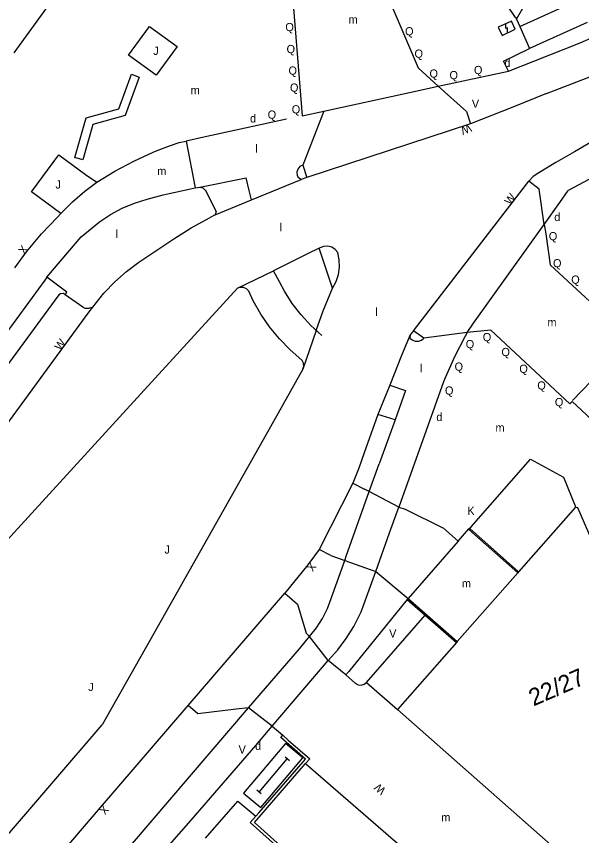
# Model space of a CAD drawing. Extents: x 134999 to 136502, y 457398 to 459002.
# Drawn here: x 135781.6 to 135816.2, y 457565.2 to 457615.2 of the extents above; entities that cross this region are included whole.
import ezdxf

# ---------------------------------------------------------------- set-up
doc = ezdxf.new("R2010")
doc.units = 0
for name, color, linetype in [('RI_DGTB_18', 7, 'Continuous'), ('RI_DGTB_2', 7, 'Continuous'), ('RI_DGTB_29', 7, 'Continuous'), ('RI_DGTB_30', 7, 'Continuous'), ('RI_DGTB_31', 7, 'Continuous'), ('RI_DGTB_32', 7, 'Continuous'), ('RI_DGTB_35', 7, 'Continuous'), ('RI_DGTB_43', 7, 'Continuous'), ('RI_DGTB_53', 7, 'Continuous')]:
    doc.layers.add(name, color=color, linetype=linetype)

msp = doc.modelspace()

# ---------------------------------------------------------------- linework, layer by layer
at = {"layer": 'RI_DGTB_18'}
msp.add_lwpolyline([(135812.201, 457615.04), (135812.669, 457615.857), (135810.956, 457618.449)], dxfattribs=at)
at = {"layer": 'RI_DGTB_2'}
for p, q in [((135812.279, 457581.22), (135808.583, 457577.024)), ((135812.332, 457581.281), (135812.279, 457581.22)), ((135808.53, 457576.964), (135804.925, 457572.871)), ((135808.583, 457577.024), (135808.53, 457576.964)), ((135818.002, 457561.354), (135804.925, 457572.871))]:
    msp.add_line(p, q, dxfattribs=at)
for points in [[(135784.404, 457617.014), (135781.488, 457612.993)], [(135815.841, 457585.222), (135815.811, 457585.23), (135812.332, 457581.281)], [(135815.945, 457585.195), (135815.841, 457585.222)], [(135824.803, 457564.892), (135820.25, 457575.305), (135819.517, 457574.985), (135818.517, 457577.282), (135819.251, 457577.601), (135815.945, 457585.195)]]:
    msp.add_lwpolyline(points, dxfattribs=at)
at = {"layer": 'RI_DGTB_29'}
for points in [[(135811.324, 457614.054), (135812.133, 457614.428), (135811.898, 457614.936), (135811.089, 457614.562), (135811.324, 457614.054)], [(135811.662, 457614.253), (135811.661, 457614.518), (135811.561, 457614.472), (135811.56, 457614.737)], [(135799.149, 457569.909), (135798.097, 457570.801), (135795.522, 457567.768), (135796.574, 457566.875), (135799.149, 457569.909)], [(135796.477, 457567.827), (135798.194, 457569.849)], [(135798.326, 457569.738), (135798.063, 457569.961)], [(135796.609, 457567.715), (135796.346, 457567.938)]]:
    msp.add_lwpolyline(points, dxfattribs=at)
at = {"layer": 'RI_DGTB_31'}
msp.add_line((135819.094, 457595.34), (135815.624, 457591.747), dxfattribs=at)
at = {"layer": 'RI_DGTB_32'}
for points in [[(135787.901, 457609.579), (135788.687, 457611.687), (135789.156, 457611.512)], [(135789.156, 457611.512), (135788.282, 457609.167)], [(135785.905, 457609.015), (135787.901, 457609.579)], [(135786.31, 457608.61), (135785.699, 457606.454), (135785.218, 457606.59), (135785.905, 457609.015)], [(135788.282, 457609.167), (135786.31, 457608.61)]]:
    msp.add_lwpolyline(points, dxfattribs=at)
at = {"layer": 'RI_DGTB_53'}
for p, q in [((135811.716, 457611.879), (135813.267, 457612.487)), ((135807.421, 457610.948), (135809.155, 457609.413)), ((135799.116, 457609.14), (135800.437, 457609.422)), ((135800.437, 457609.422), (135799.14, 457606.127)), ((135809.155, 457609.413), (135809.404, 457608.653)), ((135792.015, 457607.602), (135792.579, 457604.741)), ((135799.14, 457606.127), (135799.389, 457605.366)), ((135796.016, 457604.015), (135799.045, 457605.261)), ((135813.595, 457604.663), (135812.962, 457605.152)), ((135813.904, 457602.509), (135813.595, 457604.663)), ((135793.795, 457603.102), (135796.016, 457604.015)), ((135792.328, 457602.292), (135793.479, 457602.932)), ((135793.795, 457603.102), (135793.479, 457602.932)), ((135809.581, 457596.472), (135813.904, 457602.509)), ((135783.512, 457599.293), (135785.603, 457601.743)), ((135781.546, 457599.848), (135782.266, 457600.825)), ((135800.257, 457601.105), (135800.137, 457601.056)), ((135795.155, 457598.605), (135797.356, 457599.68)), ((135797.728, 457598.991), (135797.356, 457599.68)), ((135809.202, 457595.905), (135809.581, 457596.472)), ((135799.963, 457596.022), (135799.153, 457593.659)), ((135809.202, 457595.905), (135806.538, 457595.555)), ((135809.202, 457595.905), (135809.045, 457595.643)), ((135804.789, 457590.559), (135803.732, 457590.898)), ((135802.211, 457586.696), (135802.924, 457586.332)), ((135804.44, 457583.663), (135805.01, 457585.243)), ((135809.35, 457583.936), (135809.297, 457583.876)), ((135809.297, 457583.876), (135812.279, 457581.22)), ((135809.35, 457583.936), (135812.332, 457581.281)), ((135808.64, 457583.147), (135805.577, 457579.653)), ((135800.859, 457582.286), (135800.147, 457582.649)), ((135803.612, 457581.306), (135805.577, 457579.653)), ((135805.526, 457579.591), (135801.952, 457575.2)), ((135805.577, 457579.653), (135805.526, 457579.591)), ((135805.526, 457579.591), (135806.623, 457578.631)), ((135805.577, 457579.653), (135808.583, 457577.024)), ((135803.031, 457574.528), (135806.623, 457578.631)), ((135806.623, 457578.631), (135808.53, 457576.964)), ((135798.94, 457576.582), (135799.561, 457577.33)), ((135800.694, 457575.868), (135799.561, 457577.33)), ((135803.031, 457574.528), (135804.925, 457572.871)), ((135797.277, 457571.851), (135795.829, 457572.971)), ((135780.361, 457564.339), (135786.894, 457571.924)), ((135796.598, 457566.445), (135799.321, 457569.571)), ((135799.321, 457569.571), (135811.178, 457559.3))]:
    msp.add_line(p, q, dxfattribs=at)
for points in [[(135799.982, 457626.659), (135806.199, 457612.074), (135807.421, 457610.948)], [(135795.358, 457624.682), (135796.194, 457622.7), (135798.426, 457617.505), (135799.116, 457609.14)], [(135812.15, 457615.149), (135810.236, 457618.01)], [(135812.411, 457614.592), (135816.096, 457616.29)], [(135812.15, 457615.149), (135812.201, 457615.04)], [(135812.201, 457615.04), (135812.411, 457614.592)], [(135816.535, 457614.839), (135813.011, 457613.25)], [(135789.779, 457614.606), (135791.46, 457613.376), (135790.18, 457611.627), (135788.499, 457612.858), (135789.779, 457614.606)], [(135812.411, 457614.592), (135813.011, 457613.25)], [(135813.267, 457612.487), (135816.089, 457613.611), (135816.938, 457613.966)], [(135811.716, 457611.879), (135811.413, 457612.485), (135813.011, 457613.25)], [(135807.421, 457610.948), (135811.716, 457611.879)], [(135814.05, 457610.513), (135817.856, 457611.977)], [(135800.437, 457609.422), (135805.659, 457610.559), (135807.421, 457610.948)], [(135814.05, 457610.513), (135811.976, 457609.68), (135809.404, 457608.653)], [(135798.141, 457608.931), (135793.092, 457607.831), (135792.015, 457607.602)], [(135819.242, 457608.977), (135815.746, 457606.95), (135814.615, 457606.286), (135813.562, 457605.655)], [(135809.404, 457608.653), (135799.389, 457605.366)], [(135790.253, 457607.025), (135791.057, 457607.333), (135791.589, 457607.511), (135792.015, 457607.602)], [(135784.365, 457603.18), (135782.566, 457604.506), (135784.239, 457606.757), (135785.874, 457605.556), (135786.556, 457605.083)], [(135786.556, 457605.083), (135787.663, 457605.764), (135788.811, 457606.377), (135789.994, 457606.918), (135790.253, 457607.025)], [(135820.078, 457607.148), (135819.076, 457606.56), (135815.368, 457604.572)], [(135799.14, 457606.127), (135798.966, 457606.038), (135798.841, 457605.887), (135798.787, 457605.699), (135798.811, 457605.504), (135798.891, 457605.359)], [(135792.849, 457604.794), (135795.694, 457605.348)], [(135796.016, 457604.015), (135795.872, 457604.572), (135795.694, 457605.348)], [(135799.045, 457605.261), (135798.891, 457605.359)], [(135799.389, 457605.366), (135799.045, 457605.261)], [(135813.562, 457605.655), (135813.232, 457605.431), (135812.962, 457605.152)], [(135784.365, 457603.18), (135785.071, 457603.893), (135785.832, 457604.548), (135786.556, 457605.083)], [(135789.634, 457604.045), (135790.622, 457604.311), (135792.579, 457604.741)], [(135792.579, 457604.741), (135792.849, 457604.794)], [(135792.849, 457604.794), (135793.035, 457604.736), (135793.183, 457604.608), (135793.24, 457604.514)], [(135805.902, 457596.015), (135812.962, 457605.152)], [(135793.24, 457604.514), (135793.696, 457603.611), (135793.849, 457603.297), (135793.795, 457603.102)], [(135813.904, 457602.509), (135814.847, 457603.838), (135815.368, 457604.572)], [(135785.603, 457601.743), (135786.73, 457602.673), (135787.399, 457603.122), (135788.11, 457603.502), (135788.855, 457603.81), (135789.634, 457604.045)], [(135782.266, 457600.825), (135783.179, 457601.923), (135784.146, 457602.96), (135784.365, 457603.18)], [(135789.248, 457600.289), (135791.27, 457601.629), (135792.328, 457602.292)], [(135813.904, 457602.509), (135814, 457601.929), (135814.273, 457600.044), (135818.855, 457595.804)], [(135800.959, 457598.615), (135800.137, 457601.056), (135799.429, 457600.712), (135797.356, 457599.68)], [(135801.283, 457600.785), (135801.126, 457600.98), (135800.915, 457601.115), (135800.672, 457601.178), (135800.422, 457601.162), (135800.256, 457601.104)], [(135800.959, 457598.614), (135801.176, 457599.014), (135801.32, 457599.446), (135801.386, 457599.897), (135801.372, 457600.352), (135801.283, 457600.785)], [(135786.306, 457597.456), (135786.995, 457598.313), (135787.652, 457599.004), (135788.364, 457599.636), (135789.127, 457600.207), (135789.248, 457600.289)], [(135783.512, 457599.293), (135783.388, 457599.105), (135781.066, 457595.931), (135773.399, 457585.472), (135763.723, 457572.277), (135752.365, 457556.762)], [(135784.624, 457598.212), (135784.734, 457598.364), (135783.512, 457599.293)], [(135800.302, 457595.724), (135799.643, 457596.323), (135799.039, 457596.978), (135798.498, 457597.685), (135798.021, 457598.437), (135797.728, 457598.991)], [(135784.234, 457598.197), (135774.385, 457584.778), (135764.666, 457571.492)], [(135795.155, 457598.605), (135788.371, 457591.2), (135779.557, 457581.563), (135775.051, 457576.626), (135773.258, 457574.173)], [(135784.526, 457598.282), (135784.345, 457598.272), (135784.234, 457598.197)], [(135784.624, 457598.212), (135784.526, 457598.282)], [(135785.7, 457597.443), (135784.624, 457598.212)], [(135795.841, 457598.421), (135795.707, 457598.57), (135795.525, 457598.656), (135795.324, 457598.664), (135795.155, 457598.605)], [(135799.085, 457594.221), (135798.373, 457594.839), (135797.715, 457595.516), (135797.117, 457596.246), (135796.583, 457597.023), (135796.117, 457597.843), (135795.841, 457598.421)], [(135799.963, 457596.022), (135800.382, 457597.227), (135800.959, 457598.615)], [(135765.655, 457569.241), (135767.866, 457572.286), (135777.232, 457585.07), (135784.476, 457594.965), (135786.087, 457597.174), (135786.306, 457597.456)], [(135786.306, 457597.456), (135786.053, 457597.368), (135785.848, 457597.379), (135785.7, 457597.443)], [(135805.704, 457595.763), (135805.181, 457594.495), (135804.467, 457592.694)], [(135805.704, 457595.763), (135805.695, 457595.553), (135805.834, 457595.448)], [(135805.902, 457596.015), (135805.704, 457595.763)], [(135806.538, 457595.555), (135805.902, 457596.015)], [(135815.473, 457591.554), (135810.636, 457596.046), (135809.202, 457595.905)], [(135805.834, 457595.448), (135806.02, 457595.368), (135806.223, 457595.365), (135806.411, 457595.439), (135806.538, 457595.555)], [(135809.045, 457595.643), (135808.411, 457594.412), (135807.847, 457593.14), (135807.749, 457592.898)], [(135799.153, 457593.659), (135799.215, 457593.84), (135799.198, 457594.03), (135799.106, 457594.198), (135799.085, 457594.221)], [(135799.153, 457593.659), (135797.169, 457590.15), (135789.785, 457577.044), (135786.894, 457571.924)], [(135804.467, 457592.694), (135803.732, 457590.898)], [(135804.467, 457592.694), (135805.415, 457592.362), (135804.789, 457590.559)], [(135807.749, 457592.898), (135806.679, 457589.921), (135805.01, 457585.243)], [(135816.173, 457591.163), (135815.609, 457591.69), (135815.473, 457591.554)], [(135803.732, 457590.898), (135802.9, 457588.562), (135802.568, 457587.61), (135802.211, 457586.696)], [(135821.539, 457583.844), (135819.941, 457586.453), (135819.223, 457587.778), (135818.685, 457588.637), (135818.415, 457589.018), (135818.203, 457589.268), (135816.173, 457591.163)], [(135804.789, 457590.559), (135803.818, 457587.874)], [(135803.212, 457586.182), (135803.818, 457587.874)], [(135809.301, 457583.906), (135809.446, 457584.03), (135813.06, 457588.168), (135815.079, 457587.066), (135815.841, 457585.222)], [(135802.211, 457586.696), (135800.147, 457582.65), (135800.147, 457582.649)], [(135803.212, 457586.182), (135802.924, 457586.332)], [(135801.71, 457581.983), (135801.799, 457582.233), (135803.212, 457586.182)], [(135805.01, 457585.243), (135803.212, 457586.182)], [(135805.01, 457585.243), (135805.406, 457585.11), (135807.739, 457583.94), (135808.64, 457583.147)], [(135808.64, 457583.147), (135809.301, 457583.906)], [(135803.612, 457581.306), (135804.44, 457583.663)], [(135800.147, 457582.649), (135799.458, 457581.706), (135798.056, 457579.976)], [(135800.859, 457582.286), (135801.71, 457581.983)], [(135800.801, 457579.43), (135801.71, 457581.983)], [(135801.71, 457581.983), (135803.612, 457581.306)], [(135802.712, 457578.834), (135803.612, 457581.306)], [(135792.134, 457573.121), (135798.056, 457579.976)], [(135798.056, 457579.976), (135798.83, 457579.299), (135799.357, 457577.525), (135799.561, 457577.33)], [(135799.561, 457577.33), (135799.991, 457577.853), (135800.356, 457578.424), (135800.652, 457579.033), (135800.801, 457579.43)], [(135800.694, 457575.868), (135801.28, 457576.508), (135801.804, 457577.201), (135802.263, 457577.938), (135802.712, 457578.834)], [(135795.829, 457572.971), (135798.94, 457576.582)], [(135797.277, 457571.851), (135800.694, 457575.868)], [(135801.779, 457574.987), (135800.694, 457575.868)], [(135801.952, 457575.2), (135801.779, 457574.987)], [(135801.779, 457574.987), (135802.355, 457574.474), (135802.526, 457574.38), (135802.72, 457574.363), (135802.905, 457574.424), (135803.031, 457574.528)], [(135781.323, 457560.516), (135786.793, 457566.874), (135792.134, 457573.121)], [(135782.873, 457557.855), (135788.625, 457564.546), (135795.829, 457572.971)], [(135795.829, 457572.971), (135795.071, 457572.889), (135792.737, 457572.6), (135792.134, 457573.121)], [(135789.409, 457562.714), (135790.133, 457563.613), (135792.322, 457566.109), (135796.271, 457570.672), (135797.277, 457571.851)], [(135797.277, 457571.851), (135797.917, 457571.295)], [(135796.458, 457566.559), (135799.315, 457569.839), (135797.799, 457571.159), (135797.917, 457571.295)], [(135797.917, 457571.295), (135798.255, 457571.001)], [(135798.255, 457571.001), (135799.569, 457569.856), (135799.321, 457569.571)], [(135793.198, 457565.001), (135795.169, 457567.279), (135796.272, 457566.345)], [(135813.561, 457556.929), (135811.192, 457559.046), (135807.846, 457555.304), (135805.864, 457557.076), (135806.53, 457557.821), (135805.516, 457558.728), (135804.85, 457557.982), (135795.934, 457565.957), (135796.272, 457566.345)], [(135811.178, 457559.3), (135807.832, 457555.558), (135806.118, 457557.09), (135806.784, 457557.835), (135805.502, 457558.982), (135804.836, 457558.236), (135796.186, 457565.973), (135796.598, 457566.445)], [(135796.272, 457566.345), (135796.458, 457566.559)]]:
    msp.add_lwpolyline(points, dxfattribs=at)

# ---------------------------------------------------------------- texts
at = {"layer": 'RI_DGTB_29'}
for p in [(135811.465, 457612.131), (135795.921, 457608.737), (135814.516, 457602.712), (135807.307, 457590.494), (135796.231, 457570.398)]:
    msp.add_text('d', height=0.5, dxfattribs=at).set_placement(p)
at = {"layer": 'RI_DGTB_30'}
for s, p in [('V', (135809.477, 457609.639)), ('K', (135809.2, 457584.76)), ('V', (135804.424, 457577.268)), ('V', (135795.221, 457570.178))]:
    msp.add_text(s, height=0.5, dxfattribs=at).set_placement(p)
for s, rotation, p in [('W', 201.8478, (135809.33, 457608.666)), ('W', 53.2815, (135811.83, 457603.653)), ('X', 53.5818, (135782.125, 457600.633)), ('W', 53.7888, (135784.328, 457594.763)), ('X', 233.8625, (135799.605, 457581.908)), ('W', 138.4307, (135804.261, 457567.98)), ('X', 229.3006, (135786.956, 457567.064))]:
    msp.add_text(s, height=0.5, rotation=rotation, dxfattribs=at).set_placement(p)
at = {"layer": 'RI_DGTB_31'}
for s, p in [('Q', (135798.081, 457614.317)), ('Q', (135805.397, 457614.06)), ('J', (135790.004, 457612.862)), ('Q', (135798.155, 457612.974)), ('Q', (135805.973, 457612.692)), ('Q', (135798.272, 457611.657)), ('Q', (135806.889, 457611.476)), ('Q', (135808.111, 457611.381)), ('Q', (135809.606, 457611.692)), ('Q', (135798.362, 457610.618)), ('Q', (135798.472, 457609.291)), ('Q', (135796.999, 457608.967)), ('J', (135784.034, 457604.7)), ('Q', (135814.182, 457601.54)), ('Q', (135814.436, 457599.889)), ('Q', (135815.551, 457598.885)), ('Q', (135810.145, 457595.374)), ('Q', (135809.103, 457594.947)), ('Q', (135811.286, 457594.463)), ('Q', (135808.422, 457593.571)), ('Q', (135812.379, 457593.438)), ('Q', (135813.477, 457592.417)), ('Q', (135807.834, 457592.108)), ('Q', (135814.551, 457591.404)), ('J', (135790.692, 457582.397)), ('J', (135786.035, 457573.999))]:
    msp.add_text(s, height=0.5, dxfattribs=at).set_placement(p)
at = {"layer": 'RI_DGTB_35'}
msp.add_text('22/27', height=1.054, rotation=23.4293, dxfattribs=at).set_placement((135813.241, 457573.052))
at = {"layer": 'RI_DGTB_43'}
for s, p in [('m', (135801.942, 457614.778)), ('m', (135792.294, 457610.46)), ('l', (135796.238, 457606.899)), ('m', (135790.252, 457605.518)), ('l', (135787.705, 457601.675)), ('l', (135797.724, 457602.079)), ('l', (135803.583, 457596.919)), ('m', (135814.097, 457596.286)), ('l', (135806.31, 457593.47)), ('m', (135810.92, 457589.848)), ('m', (135808.864, 457580.325)), ('m', (135807.609, 457566.03))]:
    msp.add_text(s, height=0.5, dxfattribs=at).set_placement(p)

doc.saveas('drawing.dxf')
